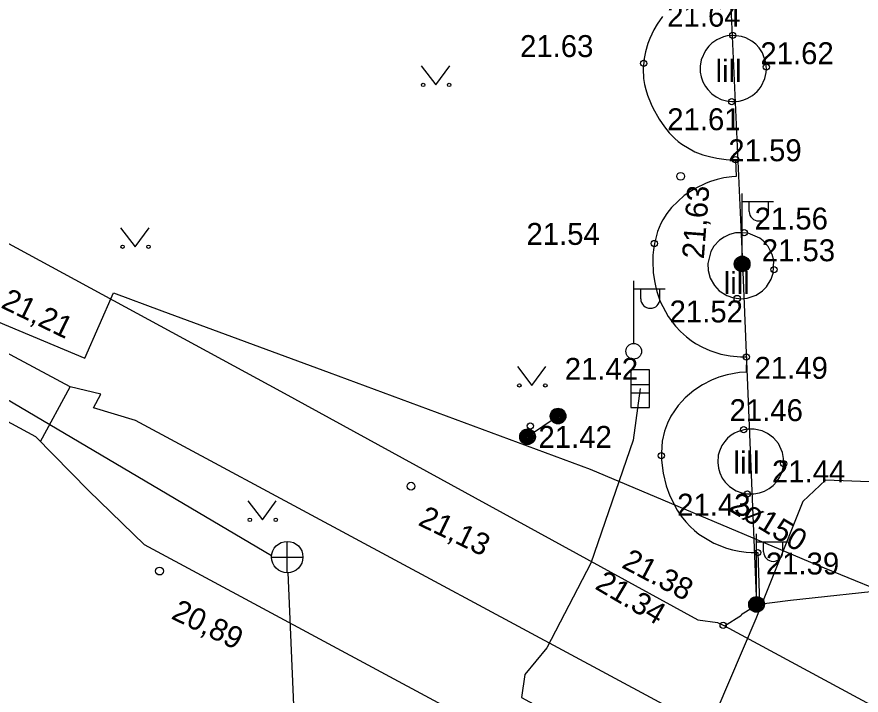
# Model space of a CAD drawing. Extents: x 714038 to 714279, y 6589845 to 6590041.
# Drawn here: x 714195.16 to 714222.12, y 6589934.18 to 6589955.84 of the extents above; entities that cross this region are included whole.
import ezdxf

# ---------------------------------------------------------------- set-up
doc = ezdxf.new("R2010")
doc.units = 0
for name, color, linetype in [('HALJASTUS', 7, 'Continuous'), ('KKAEV', 7, 'Continuous'), ('KORGUS', 7, 'Continuous'), ('KPKAABEL', 7, 'Continuous'), ('MPKAABEL', 7, 'Continuous'), ('POST', 7, 'Continuous'), ('RAJATIS', 7, 'Continuous'), ('SKTRASS', 7, 'Continuous'), ('TEE', 7, 'Continuous'), ('TORU NR', 7, 'Continuous'), ('TTRASS', 7, 'Continuous')]:
    doc.layers.add(name, color=color, linetype=linetype)

msp = doc.modelspace()

# ---------------------------------------------------------------- linework, layer by layer
at = {"layer": 'HALJASTUS'}
for p, q in [((714208.077, 6589954.277), (714208.54, 6589953.67)), ((714208.54, 6589953.67), (714208.986, 6589954.277)), ((714198.477, 6589949.107), (714198.94, 6589948.5)), ((714198.94, 6589948.5), (714199.386, 6589949.107)), ((714211.147, 6589944.677), (714211.61, 6589944.07)), ((714211.61, 6589944.07), (714212.056, 6589944.677)), ((714202.539, 6589940.384), (714203.002, 6589939.778)), ((714203.002, 6589939.778), (714203.448, 6589940.384))]:
    msp.add_line(p, q, dxfattribs=at)
for centre in [(714208.139, 6589953.67), (714208.968, 6589953.67), (714198.539, 6589948.5), (714199.368, 6589948.5), (714211.209, 6589944.07), (714212.038, 6589944.07), (714202.601, 6589939.778), (714203.43, 6589939.778)]:
    msp.add_circle(centre, 0.055, dxfattribs=at)
at = {"layer": 'KKAEV'}
for p, q in [((714203.798, 6589938.088), (714203.798, 6589939.088)), ((714203.298, 6589938.588), (714204.298, 6589938.588))]:
    msp.add_line(p, q, dxfattribs=at)
msp.add_circle((714203.798, 6589938.588), 0.5, dxfattribs=at)
at = {"layer": 'KORGUS'}
for centre, radius in [((714218.019, 6589955.251), 0.1), ((714215.176, 6589954.356), 0.1), ((714219.099, 6589954.245), 0.1), ((714217.992, 6589953.137), 0.1), ((714218.111, 6589951.28), 0.1), ((714216.36, 6589950.75), 0.125), ((714218.392, 6589948.949), 0.1), ((714215.522, 6589948.604), 0.1), ((714219.337, 6589947.765), 0.1), ((714218.165, 6589946.846), 0.1), ((714218.459, 6589944.981), 0.1), ((714211.558, 6589942.776), 0.1), ((714218.373, 6589942.654), 0.1), ((714215.745, 6589941.826), 0.1), ((714219.649, 6589941.569), 0.1), ((714207.75, 6589940.85), 0.125), ((714218.491, 6589940.605), 0.1), ((714218.82, 6589938.731), 0.1), ((714199.72, 6589938.14), 0.125), ((714217.718, 6589936.403), 0.1)]:
    msp.add_circle(centre, radius, dxfattribs=at)
at = {"layer": 'KPKAABEL'}
msp.add_lwpolyline([(714278.95, 6590013.083), (714274.696, 6590002.154), (714268.806, 6589986.746), (714264.689, 6589977.209), (714260.118, 6589965.851), (714258.032, 6589961.24), (714253.05, 6589949.372), (714248.466, 6589938.096), (714247.531, 6589934.989), (714246.389, 6589934.367), (714239.483, 6589937.254), (714226.492, 6589940.819), (714222.669, 6589940.979), (714220.982, 6589941.049), (714220.257, 6589940.365), (714218.76, 6589936.611), (714215.836, 6589929.757), (714212.225, 6589922.206), (714208.098, 6589916.26), (714202.344, 6589907.69)], dxfattribs=at)
at = {"layer": 'MPKAABEL'}
for points in [[(714167.029, 6589999.261), (714167.805, 6589985.535), (714167.801, 6589985.524), (714168.701, 6589969.69), (714168.856, 6589964.517), (714181.003, 6589963.765), (714182.873, 6589963.649), (714187.834, 6589963.342), (714201.122, 6589963.986), (714214.138, 6589964.636), (714217.634, 6589964.759), (714217.843, 6589958.743), (714218.335, 6589947.958), (714218.782, 6589937.076), (714219.871, 6589937.206), (714226.57, 6589937.936), (714228.214, 6589938.132), (714236.763, 6589938.683), (714246.845, 6589940.926), (714247.938, 6589921.303)], [(714215.066, 6589943.967), (714214.846, 6589942.32), (714213.494, 6589938.395), (714212.085, 6589935.688), (714211.383, 6589934.84), (714211.278, 6589934.105), (714212.162, 6589933.623), (714233.552, 6589922.923), (714249.701, 6589913.675), (714250.295, 6589914.005), (714250.521, 6589914.785), (714251.05, 6589918.335), (714251.513, 6589923.366), (714251.481, 6589924.441), (714250.114, 6589927.476), (714252.56, 6589933.122), (714254.403, 6589936.762), (714260.237, 6589952.896), (714261.787, 6589959.195)]]:
    msp.add_lwpolyline(points, dxfattribs=at)
at = {"layer": 'POST'}
for p, q in [((714218.323, 6589948.2), (714218.323, 6589950.2)), ((714218.323, 6589949.95), (714219.323, 6589949.95)), ((714218.55, 6589949.629), (714218.55, 6589949.95)), ((714219.162, 6589949.629), (714219.162, 6589949.95)), ((714214.86, 6589945.41), (714214.86, 6589947.41)), ((714214.86, 6589947.16), (714215.86, 6589947.16)), ((714215.087, 6589946.839), (714215.087, 6589947.16)), ((714215.699, 6589946.839), (714215.699, 6589947.16)), ((714215.365, 6589944.564), (714214.768, 6589944.564)), ((714214.768, 6589944.564), (714214.768, 6589943.369)), ((714215.365, 6589943.369), (714215.365, 6589944.564)), ((714214.768, 6589944.102), (714215.365, 6589944.102)), ((714214.768, 6589943.831), (714215.365, 6589943.831)), ((714214.768, 6589943.369), (714215.365, 6589943.369)), ((714218.782, 6589937.326), (714218.782, 6589939.326)), ((714218.782, 6589939.076), (714219.782, 6589939.076)), ((714219.009, 6589938.755), (714219.009, 6589939.076)), ((714219.621, 6589938.755), (714219.621, 6589939.076))]:
    msp.add_line(p, q, dxfattribs=at)
for centre, radius in [((714218.323, 6589947.95), 0.25), ((714218.323, 6589947.95), 0.225), ((714218.323, 6589947.95), 0.2), ((714218.323, 6589947.95), 0.175), ((714218.323, 6589947.95), 0.15), ((714218.323, 6589947.95), 0.125), ((714218.323, 6589947.95), 0.1), ((714218.323, 6589947.95), 0.075), ((714218.323, 6589947.95), 0.05), ((714218.323, 6589947.95), 0.025), ((714214.86, 6589945.16), 0.25), ((714218.782, 6589937.076), 0.25), ((714218.782, 6589937.076), 0.225), ((714218.782, 6589937.076), 0.2), ((714218.782, 6589937.076), 0.175), ((714218.782, 6589937.076), 0.15), ((714218.782, 6589937.076), 0.125), ((714218.782, 6589937.076), 0.1), ((714218.782, 6589937.076), 0.075), ((714218.782, 6589937.076), 0.05), ((714218.782, 6589937.076), 0.025)]:
    msp.add_circle(centre, radius, dxfattribs=at)
for centre in [(714218.856, 6589949.629), (714215.393, 6589946.839), (714219.315, 6589938.755)]:
    msp.add_arc(centre, 0.306, 180, 0, dxfattribs=at)
at = {"layer": 'RAJATIS'}
for centre, radius in [((714212.444, 6589943.09), 0.25), ((714212.444, 6589943.09), 0.225), ((714212.444, 6589943.09), 0.2), ((714212.444, 6589943.09), 0.175), ((714212.444, 6589943.09), 0.15), ((714212.444, 6589943.09), 0.125), ((714212.444, 6589943.09), 0.1), ((714212.444, 6589943.09), 0.075), ((714212.444, 6589943.09), 0.05), ((714212.444, 6589943.09), 0.025), ((714211.47, 6589942.43), 0.25), ((714211.47, 6589942.43), 0.225), ((714211.47, 6589942.43), 0.2), ((714211.47, 6589942.43), 0.175), ((714211.47, 6589942.43), 0.15), ((714211.47, 6589942.43), 0.125), ((714211.47, 6589942.43), 0.1), ((714211.47, 6589942.43), 0.075), ((714211.47, 6589942.43), 0.05), ((714211.47, 6589942.43), 0.025)]:
    msp.add_circle(centre, radius, dxfattribs=at)
at = {"layer": 'SKTRASS'}
for points in [[(714161.935, 6589963.885), (714185.098, 6589949.388), (714203.298, 6589938.638), (714203.3, 6589938.638)], [(714203.819, 6589938.089), (714204.081, 6589931.863)]]:
    msp.add_lwpolyline(points, dxfattribs=at)
at = {"layer": 'TEE'}
for points in [[(714215.778, 6589955.853), (714215.614, 6589955.612), (714215.506, 6589955.424), (714215.379, 6589955.157), (714215.315, 6589954.988), (714215.24, 6589954.728), (714215.197, 6589954.514), (714215.165, 6589954.185), (714215.177, 6589953.874), (714215.205, 6589953.683), (714215.243, 6589953.518), (714215.298, 6589953.343), (714215.416, 6589953.05), (714215.468, 6589952.94), (714215.675, 6589952.572), (714215.844, 6589952.327), (714215.992, 6589952.143), (714216.174, 6589951.956), (714216.285, 6589951.86), (714216.393, 6589951.778), (714216.816, 6589951.537), (714217.065, 6589951.441), (714217.276, 6589951.378), (714217.518, 6589951.326), (714217.812, 6589951.289), (714218.004, 6589951.28), (714218.111, 6589951.28), (714218.127, 6589950.745), (714217.991, 6589950.734), (714217.735, 6589950.697), (714217.523, 6589950.649), (714217.318, 6589950.587), (714217.179, 6589950.536), (714216.821, 6589950.366), (714216.471, 6589950.136), (714216.068, 6589949.759), (714215.918, 6589949.563), (714215.794, 6589949.364), (714215.728, 6589949.238), (714215.623, 6589948.986), (714215.522, 6589948.604), (714215.492, 6589948.406), (714215.476, 6589948.227), (714215.469, 6589948.041), (714215.484, 6589947.674), (714215.52, 6589947.41), (714215.553, 6589947.248), (714215.6, 6589947.066), (714215.71, 6589946.75), (714215.961, 6589946.274), (714216.196, 6589945.96), (714216.356, 6589945.789), (714216.546, 6589945.618), (714216.7, 6589945.501), (714216.835, 6589945.412), (714217.058, 6589945.287), (714217.291, 6589945.185), (714217.64, 6589945.073), (714217.937, 6589945.013), (714218.266, 6589944.982), (714218.459, 6589944.981), (714218.453, 6589944.498), (714218.238, 6589944.481), (714217.847, 6589944.41), (714217.58, 6589944.329), (714217.343, 6589944.234), (714217.053, 6589944.084), (714216.781, 6589943.903), (714216.504, 6589943.67), (714216.395, 6589943.559), (714216.278, 6589943.425), (714216.05, 6589943.085), (714215.943, 6589942.869), (714215.849, 6589942.614), (714215.774, 6589942.287), (714215.744, 6589941.921), (714215.753, 6589941.68), (714215.804, 6589941.272), (714215.902, 6589940.863), (714216.016, 6589940.538), (714216.246, 6589940.088), (714216.376, 6589939.898), (714216.526, 6589939.711), (714216.668, 6589939.561), (714216.801, 6589939.438), (714216.943, 6589939.322), (714217.417, 6589939.031), (714217.823, 6589938.871), (714218.019, 6589938.817), (714218.233, 6589938.773), (714218.453, 6589938.744), (714218.606, 6589938.733), (714218.82, 6589938.731), (714218.882, 6589937.107), (714218.293, 6589936.747)], [(714182.127, 6589955.541), (714203.579, 6589943.89), (714216.913, 6589936.58), (714217.539, 6589936.495), (714217.759, 6589936.392), (714218.3, 6589936.729)], [(714217.846, 6589955.234), (714217.728, 6589955.205), (714217.515, 6589955.113), (714217.357, 6589955.003), (714217.259, 6589954.909), (714217.148, 6589954.766), (714217.018, 6589954.472), (714216.983, 6589954.267), (714216.987, 6589954.079), (714217.013, 6589953.933), (714217.07, 6589953.768), (714217.151, 6589953.619), (714217.225, 6589953.518), (714217.352, 6589953.39), (714217.498, 6589953.286), (714217.653, 6589953.209), (714217.862, 6589953.151), (714217.996, 6589953.137), (714218.133, 6589953.14), (714218.223, 6589953.152), (714218.343, 6589953.18), (714218.484, 6589953.233), (714218.655, 6589953.332), (714218.804, 6589953.46), (714218.87, 6589953.536), (714218.929, 6589953.617), (714219.052, 6589953.879), (714219.092, 6589954.062), (714219.1, 6589954.174), (714219.082, 6589954.391), (714218.975, 6589954.692), (714218.871, 6589954.851), (714218.763, 6589954.968), (714218.636, 6589955.069), (714218.445, 6589955.171), (714218.303, 6589955.219), (714218.045, 6589955.252), (714217.846, 6589955.234)], [(714195.915, 6589942.281), (714196.868, 6589944.026), (714183.617, 6589951.131), (714182.568, 6589949.15)], [(714218.517, 6589948.929), (714218.323, 6589948.946), (714218.112, 6589948.941), (714217.923, 6589948.891), (714217.751, 6589948.811), (714217.602, 6589948.706), (714217.424, 6589948.514), (714217.327, 6589948.349), (714217.228, 6589947.97), (714217.238, 6589947.737), (714217.305, 6589947.494), (714217.438, 6589947.262), (714217.592, 6589947.097), (714217.833, 6589946.941), (714218.046, 6589946.867), (714218.3, 6589946.839), (714218.482, 6589946.857), (714218.771, 6589946.957), (714218.969, 6589947.088), (714219.101, 6589947.221), (714219.254, 6589947.468), (714219.317, 6589947.653), (714219.333, 6589948.058), (714219.283, 6589948.255), (714219.151, 6589948.507), (714218.993, 6589948.685), (714218.884, 6589948.77), (714218.517, 6589948.929)], [(714263.275, 6589906.612), (714262.481, 6589906.156), (714261.368, 6589906.05), (714260.213, 6589906.315), (714240.788, 6589916.652), (714217.995, 6589928.881), (714199.241, 6589938.974), (714197.452, 6589940.713), (714195.768, 6589942.431), (714184.455, 6589948.554)], [(714263.275, 6589906.612), (714263.414, 6589907.94), (714262.577, 6589908.551), (714241.037, 6589920.211), (714219.611, 6589931.838), (714198.955, 6589942.945), (714197.611, 6589943.352), (714197.847, 6589943.789), (714196.868, 6589944.026)], [(714212.444, 6589943.09), (714211.47, 6589942.43)], [(714218.083, 6589942.548), (714217.975, 6589942.481), (714217.857, 6589942.383), (714217.768, 6589942.284), (714217.675, 6589942.147), (714217.596, 6589941.97), (714217.562, 6589941.841), (714217.542, 6589941.61), (714217.564, 6589941.427), (714217.606, 6589941.281), (714217.688, 6589941.11), (714217.78, 6589940.982), (714217.923, 6589940.84), (714218.128, 6589940.708), (714218.318, 6589940.637), (714218.491, 6589940.605), (714218.694, 6589940.604), (714218.875, 6589940.637), (714219.036, 6589940.694), (714219.182, 6589940.774), (714219.31, 6589940.873), (714219.434, 6589941.006), (714219.515, 6589941.127), (714219.587, 6589941.279), (714219.641, 6589941.491), (714219.647, 6589941.731), (714219.61, 6589941.93), (714219.479, 6589942.214), (714219.324, 6589942.398), (714219.135, 6589942.539), (714218.959, 6589942.621), (714218.71, 6589942.676), (714218.511, 6589942.677), (714218.373, 6589942.654), (714218.176, 6589942.593), (714218.083, 6589942.548)], [(714217.759, 6589936.392), (714238.65, 6589925.109), (714247.372, 6589920.348), (714247.69, 6589919.978), (714264.11, 6589911.01), (714265.191, 6589911.398), (714265.199, 6589917.222), (714265.151, 6589925.259), (714246.63, 6589937.111), (714247.349, 6589920.604), (714247.372, 6589920.348)]]:
    msp.add_lwpolyline(points, dxfattribs=at)
at = {"layer": 'TTRASS'}
msp.add_lwpolyline([(714180.868, 6589954.471), (714194.81, 6589948.35), (714193.9, 6589946.38), (714197.33, 6589944.94), (714198.25, 6589947.03), (714199.797, 6589946.458), (714205.14, 6589944.481), (714213.47, 6589941.4), (714220.708, 6589938.334), (714228.631, 6589935.107), (714230.913, 6589934.185)], dxfattribs=at)

# ---------------------------------------------------------------- texts
at = {"layer": 'HALJASTUS'}
for p in [(714217.474, 6589953.767), (714217.735, 6589946.991), (714218.047, 6589941.256)]:
    msp.add_text('lill', height=0.7, dxfattribs=at).set_placement(p)
at = {"layer": 'KORGUS'}
for s, p in [(' 21.64', (714215.671, 6589955.53)), (' 21.63', (714210.971, 6589954.56)), (' 21.62', (714218.645, 6589954.332)), (' 21.61', (714215.671, 6589952.223)), (' 21.59', (714217.622, 6589951.232)), (' 21.56', (714218.46, 6589949.05)), (' 21.54', (714211.175, 6589948.56)), (' 21.53', (714218.689, 6589948.037)), (' 21.52', (714215.747, 6589946.083)), (' 21.42', (714212.398, 6589944.249)), (' 21.49', (714218.459, 6589944.281)), (' 21.46 ', (714217.661, 6589942.929)), (' 21.42', (714211.558, 6589942.076)), (' 21.44', (714219.016, 6589940.974)), (' 21.43', (714215.987, 6589939.911)), (' 21.39', (714218.82, 6589938.031))]:
    msp.add_text(s, height=0.7, dxfattribs=at).set_placement(p)
for s, rotation, p in [('21,63', 85.6457, (714217.1, 6589948.095)), ('21,21', 334.0139, (714194.621, 6589946.571)), ('21,13', 334.0139, (714207.943, 6589939.625)), (' 21.38', 332.0961, (714214.213, 6589938.391)), (' 21.34', 329.3897, (714213.366, 6589937.725)), ('20,89', 334.0139, (714200.058, 6589936.637))]:
    msp.add_text(s, height=0.7, rotation=rotation, dxfattribs=at).set_placement(p)
at = {"layer": 'TORU NR'}
msp.add_text('2ø150', height=0.7, rotation=328.9855, dxfattribs=at).set_placement((714217.839, 6589940.103))

doc.saveas('drawing.dxf')
